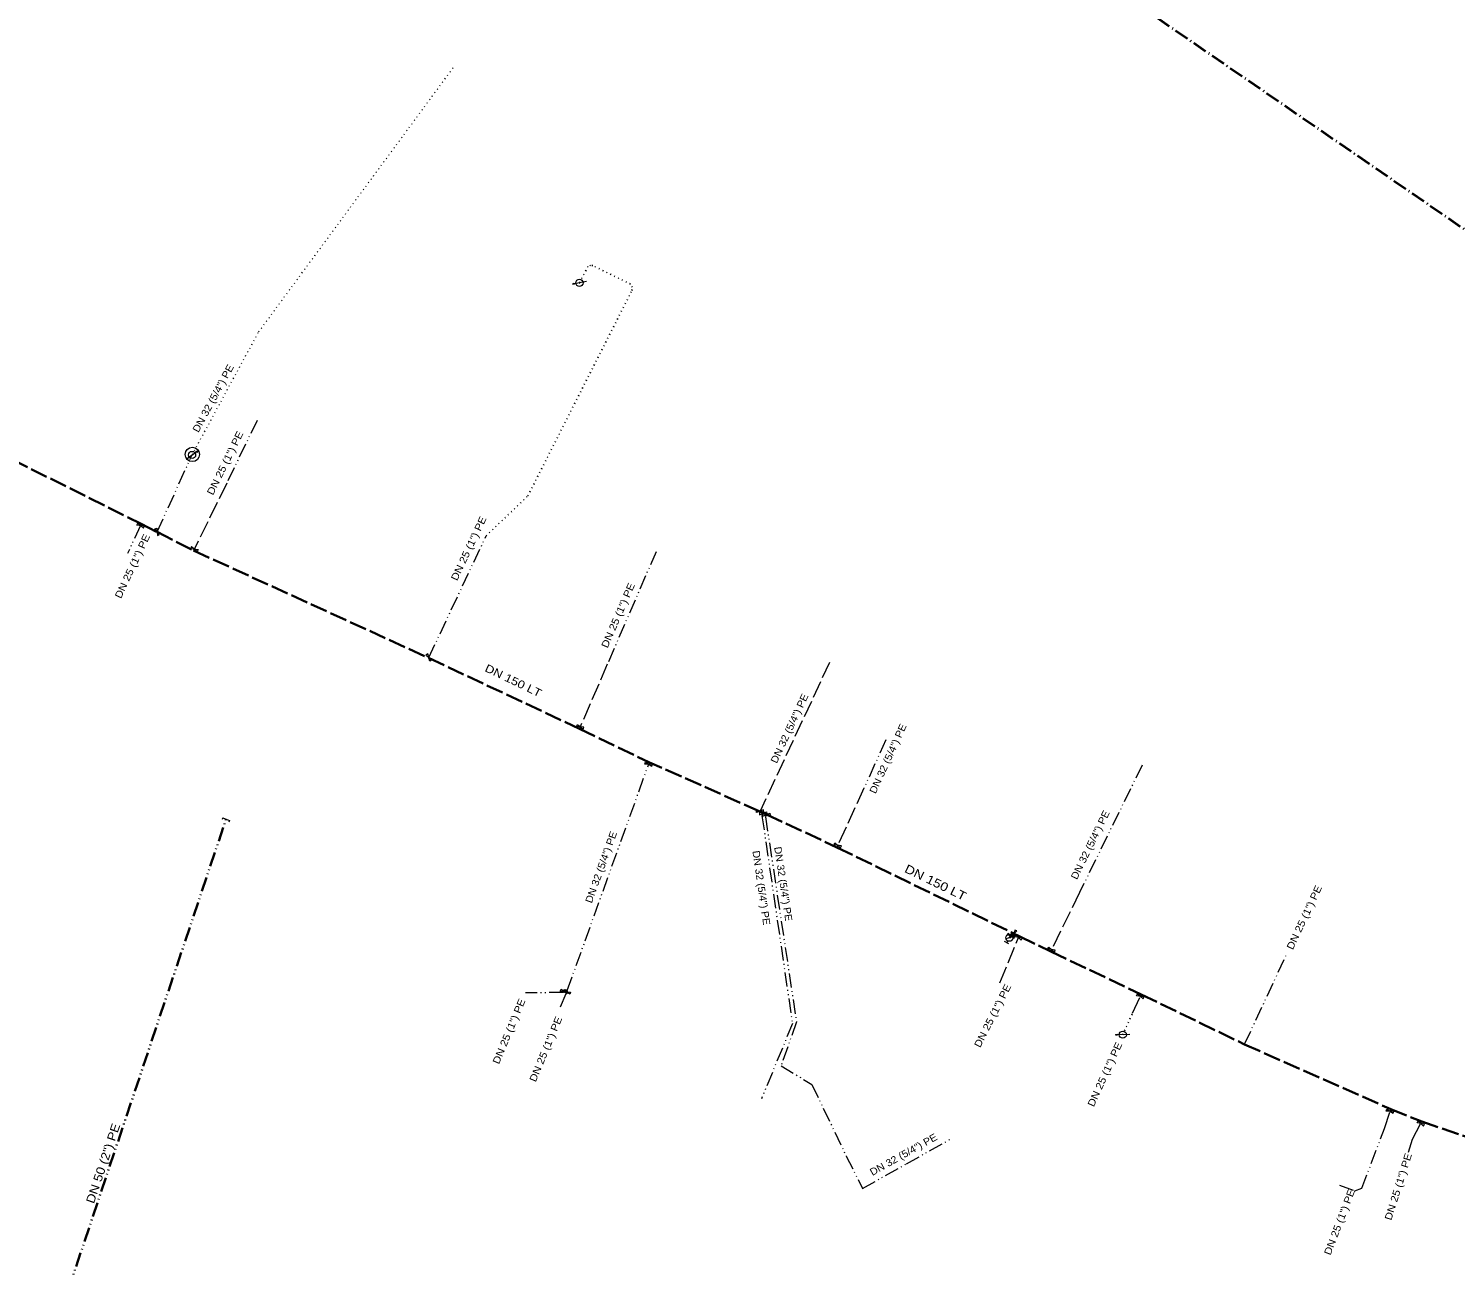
# Model space of a CAD drawing. Extents: x -635202 to -632824, y -1037605 to -1036177.
# Drawn here: x -634347.6 to -634148.5, y -1037187.1 to -1037014.4 of the extents above; entities that cross this region are included whole.
import ezdxf
from ezdxf.enums import TextEntityAlignment as Align

# ---------------------------------------------------------------- set-up
doc = ezdxf.new("R2010")
doc.units = 0
doc.header["$LTSCALE"] = 0.4
for name, pattern in [('DASH_DOUBLE_DOT', [9.2, 5, -1.2, 0.3, -1.2, 0.3, -1.2]), ('DOT_DASHED', [7.7, 5, -1.2, 0.3, -1.2]), ('DOTTED', [1.5, 0.3, -1.2]), ('LONG_DASHED', [7.5, 6, -1.5])]:
    doc.linetypes.add(name, pattern=pattern)
for name, color, linetype, lineweight in [('10', 7, 'Continuous', 13), ('12', 7, 'Continuous', 13), ('21', 7, 'LONG_DASHED', 35), ('22', 7, 'DASH_DOUBLE_DOT', 35), ('31', 7, 'LONG_DASHED', 13), ('32', 7, 'DASH_DOUBLE_DOT', 13), ('63', 7, 'DOT_DASHED', 40)]:
    doc.layers.add(name, color=color, linetype=linetype, lineweight=lineweight)
doc.layers.add('29', color=7, linetype='Continuous')
doc.layers.add('39', color=7, linetype='Continuous')

msp = doc.modelspace()

# ---------------------------------------------------------------- linework, layer by layer
at = {"layer": '10'}
for p, q in [((-634269.769, -1037049.723), (-634271.735, -1037050.094)), ((-634320.521, -1037124.53), (-634320.605, -1037124.765)), ((-634320.521, -1037124.53), (-634319.579, -1037124.864)), ((-634319.579, -1037124.864), (-634319.663, -1037125.1)), ((-634210.845, -1037142.104), (-634211.463, -1037141.775)), ((-634210.3, -1037141.087), (-634211.256, -1037141.379)), ((-634211.013, -1037141.674), (-634211.154, -1037141.939)), ((-634193.959, -1037154.713), (-634195.957, -1037154.796))]:
    msp.add_line(p, q, dxfattribs=at)
for points in [[(-634271.439, -1037050.143), (-634271.735, -1037050.094), (-634271.478, -1037049.94)], [(-634195.672, -1037154.888), (-634195.957, -1037154.796), (-634195.681, -1037154.682)]]:
    msp.add_lwpolyline(points, dxfattribs=at)
for points in [[(-634331.466, -1037083.828), (-634332.501, -1037083.689), (-634332.377, -1037083.416), (-634331.59, -1037084.102)], [(-634329.32, -1037085.018), (-634329.996, -1037084.222), (-634329.721, -1037084.101), (-634329.595, -1037085.138)], [(-634324.982, -1037086.931), (-634323.95, -1037087.091), (-634324.08, -1037087.362), (-634324.853, -1037086.66)], [(-634292.161, -1037101.814), (-634291.384, -1037102.512), (-634291.641, -1037102.668), (-634291.905, -1037101.657)], [(-634270.125, -1037111.875), (-634271.162, -1037111.753), (-634271.043, -1037111.478), (-634270.245, -1037112.151)], [(-634260.568, -1037117.043), (-634261.612, -1037117.03), (-634261.523, -1037116.744), (-634260.658, -1037117.33)], [(-634245.061, -1037123.377), (-634246.03, -1037123.764), (-634246.057, -1037123.465), (-634245.034, -1037123.675)], [(-634245.613, -1037124.078), (-634244.653, -1037123.665), (-634244.619, -1037123.964), (-634245.647, -1037123.78)], [(-634245.154, -1037124.294), (-634244.2, -1037123.871), (-634244.162, -1037124.168), (-634245.193, -1037123.997)], [(-634234.194, -1037128.426), (-634235.229, -1037128.288), (-634235.106, -1037128.014), (-634234.318, -1037128.699)], [(-634210.022, -1037140.155), (-634210.19, -1037141.185), (-634210.46, -1037141.054), (-634209.752, -1037140.286)], [(-634210.035, -1037141.052), (-634211.065, -1037140.884), (-634210.934, -1037140.614), (-634210.166, -1037141.321)], [(-634208.987, -1037141.302), (-634210.011, -1037141.1), (-634209.871, -1037140.835), (-634209.127, -1037141.567)], [(-634204.368, -1037142.967), (-634205.398, -1037142.796), (-634205.265, -1037142.527), (-634204.5, -1037143.236)], [(-634272.378, -1037148.743), (-634273.422, -1037148.701), (-634273.324, -1037148.418), (-634272.476, -1037149.026)], [(-634273.051, -1037148.771), (-634272.009, -1037148.827), (-634272.11, -1037149.11), (-634272.95, -1037148.488)], [(-634191.997, -1037149.487), (-634193.031, -1037149.341), (-634192.906, -1037149.069), (-634192.123, -1037149.76)], [(-634157.155, -1037165.43), (-634158.199, -1037165.415), (-634158.108, -1037165.129), (-634157.245, -1037165.716)], [(-634152.868, -1037167.24), (-634153.893, -1037167.041), (-634153.753, -1037166.776), (-634153.007, -1037167.506)]]:
    msp.add_lwpolyline(points, close=True, dxfattribs=at)
for centre, radius in [((-634270.752, -1037049.908), 0.5), ((-634324.7521, -1037073.8308), 1), ((-634210.7789, -1037141.2331), 0.5), ((-634194.958, -1037154.754), 0.5)]:
    msp.add_circle(centre, radius, dxfattribs=at)
at = {"layer": '12'}
msp.add_line((-634325.612, -1037074.485), (-634323.978, -1037073.331), dxfattribs=at)
msp.add_lwpolyline([(-634324.268, -1037073.41), (-634323.978, -1037073.331), (-634324.15, -1037073.577)], dxfattribs=at)
msp.add_circle((-634324.7949, -1037073.9078), 0.5, dxfattribs=at)
at = {"layer": '21'}
for p, q in [((-634371.382, -1037063.807), (-634331.877, -1037083.532)), ((-634331.877, -1037083.532), (-634329.672, -1037084.651)), ((-634329.672, -1037084.651), (-634324.576, -1037087.236)), ((-634324.576, -1037087.236), (-634291.795, -1037102.21)), ((-634291.795, -1037102.21), (-634270.759, -1037112.091)), ((-634270.759, -1037112.091), (-634261.001, -1037116.773)), ((-634245.566, -1037123.615), (-634261.001, -1037116.773)), ((-634244.66, -1037124.039), (-634234.828, -1037128.632)), ((-634234.828, -1037128.632), (-634210.348, -1037140.552)), ((-634210.55, -1037140.968), (-634210.779, -1037141.233)), ((-634210.348, -1037140.552), (-634210.55, -1037140.968)), ((-634210.106, -1037140.67), (-634209.401, -1037141.013)), ((-634209.401, -1037141.013), (-634205.007, -1037143.153)), ((-634205.007, -1037143.153), (-634192.38, -1037149.146)), ((-634177.973, -1037156.1), (-634157.582, -1037165.138)), ((-634157.582, -1037165.138), (-634153.252, -1037166.87)), ((-634153.252, -1037166.87), (-634141.09, -1037171.014))]:
    msp.add_line(p, q, dxfattribs=at)
for points in [[(-634245.566, -1037123.615), (-634245.113, -1037123.827), (-634245.113, -1037123.827)], [(-634245.113, -1037123.827), (-634244.66, -1037124.039), (-634244.66, -1037124.039)], [(-634210.348, -1037140.552), (-634210.106, -1037140.67), (-634210.106, -1037140.67)], [(-634192.38, -1037149.146), (-634177.973, -1037156.1), (-634177.973, -1037156.1)]]:
    msp.add_lwpolyline(points, dxfattribs=at)
at = {"layer": '22'}
msp.add_lwpolyline([(-634345.987, -1037202.012), (-634342.145, -1037190.56), (-634320.05, -1037124.697)], dxfattribs=at)
at = {"layer": '31'}
for p, q in [((-634319.963, -1037077.857), (-634324.466, -1037087.011)), ((-634324.466, -1037087.011), (-634324.576, -1037087.236)), ((-634266.866, -1037103.1), (-634270.644, -1037111.814)), ((-634235.859, -1037102.837), (-634245.545, -1037123.57)), ((-634270.644, -1037111.814), (-634270.759, -1037112.091)), ((-634261.09, -1037117.037), (-634261.001, -1037116.773)), ((-634231.07, -1037120.378), (-634234.712, -1037128.357)), ((-634245.545, -1037123.57), (-634245.566, -1037123.615)), ((-634234.712, -1037128.357), (-634234.828, -1037128.632)), ((-634200.976, -1037134.923), (-634204.883, -1037142.882)), ((-634212.085, -1037147.525), (-634209.499, -1037141.201)), ((-634209.499, -1037141.201), (-634209.401, -1037141.013)), ((-634204.883, -1037142.882), (-634205.007, -1037143.153)), ((-634193.591, -1037151.755), (-634192.514, -1037149.414)), ((-634192.514, -1037149.414), (-634192.38, -1037149.146)), ((-634158.438, -1037167.828), (-634157.677, -1037165.422)), ((-634157.677, -1037165.422), (-634157.582, -1037165.138)), ((-634154.519, -1037169.312), (-634153.38, -1037167.141)), ((-634153.38, -1037167.141), (-634153.252, -1037166.87))]:
    msp.add_line(p, q, dxfattribs=at)
at = {"layer": '32', "linetype": 'DOTTED', "lineweight": 25}
for p, q in [((-634270.752, -1037049.908), (-634270.984, -1037050.351)), ((-634194.958, -1037154.754), (-634193.591, -1037151.755)), ((-634195.165, -1037155.209), (-634194.958, -1037154.754))]:
    msp.add_line(p, q, dxfattribs=at)
at = {"layer": '32'}
for p, q in [((-634324.794, -1037073.908), (-634324.752, -1037073.831)), ((-634331.983, -1037083.759), (-634333.799, -1037087.653)), ((-634331.877, -1037083.532), (-634331.983, -1037083.759)), ((-634329.672, -1037084.651), (-634329.658, -1037084.619)), ((-634291.773, -1037102.163), (-634283.761, -1037085.18)), ((-634260.061, -1037087.402), (-634266.866, -1037103.1)), ((-634291.795, -1037102.21), (-634291.773, -1037102.163)), ((-634272.447, -1037148.569), (-634261.09, -1037117.037)), ((-634192.261, -1037117.167), (-634200.976, -1037134.923)), ((-634245.113, -1037123.827), (-634245.133, -1037123.872)), ((-634244.66, -1037124.039), (-634244.677, -1037124.083)), ((-634177.952, -1037156.055), (-634172.191, -1037143.759)), ((-634272.53, -1037148.799), (-634272.447, -1037148.569)), ((-634225.111, -1037172.751), (-634219.064, -1037169.366)), ((-634155.083, -1037171.115), (-634154.519, -1037169.312))]:
    msp.add_line(p, q, dxfattribs=at)
at = {"layer": '32', "linetype": 'DOTTED'}
msp.add_lwpolyline([(-634324.752, -1037073.831), (-634315.507, -1037056.745), (-634288.263, -1037019.766)], dxfattribs=at)
at = {"layer": '32', "linetype": 'DOTTED', "lineweight": 25}
msp.add_lwpolyline([(-634283.761, -1037085.18), (-634277.946, -1037079.613), (-634263.425, -1037050.966), (-634263.394, -1037050.526), (-634263.645, -1037050.07), (-634268.894, -1037047.508), (-634269.208, -1037047.461), (-634269.554, -1037047.618), (-634270.752, -1037049.908)], dxfattribs=at)
at = {"layer": '32'}
for points in [[(-634315.73, -1037069.098), (-634319.963, -1037077.857), (-634319.963, -1037077.857)], [(-634329.658, -1037084.619), (-634324.842, -1037073.997), (-634324.794, -1037073.908)], [(-634227.993, -1037113.655), (-634231.07, -1037120.378), (-634231.07, -1037120.378)], [(-634245.133, -1037123.872), (-634245.288, -1037124.218), (-634241.04, -1037153.216), (-634245.35, -1037163.688)], [(-634244.677, -1037124.083), (-634244.797, -1037124.383), (-634240.476, -1037152.977), (-634242.624, -1037159.085), (-634238.328, -1037161.691), (-634233.538, -1037171.676), (-634231.249, -1037176.187), (-634225.111, -1037172.751)], [(-634272.9, -1037148.722), (-634272.972, -1037148.886), (-634278.266, -1037148.903)], [(-634273.396, -1037150.876), (-634272.53, -1037148.799), (-634272.53, -1037148.799)], [(-634272.447, -1037148.569), (-634272.691, -1037148.49), (-634272.832, -1037148.524), (-634272.9, -1037148.722)], [(-634177.973, -1037156.1), (-634177.952, -1037156.055), (-634177.952, -1037156.055)], [(-634164.705, -1037175.734), (-634162.582, -1037176.526), (-634161.6, -1037176.154), (-634158.438, -1037167.828)]]:
    msp.add_lwpolyline(points, dxfattribs=at)
at = {"layer": '63'}
msp.add_lwpolyline([(-635201.893, -1036293.521), (-635065.737, -1036176.522), (-634666.247, -1036562.377), (-634740.782, -1036634.185), (-633954.528, -1037175.019), (-633883.629, -1037007.77), (-632823.776, -1037286.822), (-632902.856, -1037604.96), (-633921.805, -1037365.902), (-634067.239, -1037477.705), (-635033.469, -1036827.795), (-634902.578, -1036625.096)], close=True, dxfattribs=at)

# ---------------------------------------------------------------- texts
at = {"layer": '29', "width": 1.2}
for height, rotation, p in [(1.1, 334.325, (-634280.2133, -1037105.8654)), (1.2, 334.037, (-634221.3327, -1037134.065))]:
    msp.add_text('DN 150 LT', height=height, rotation=rotation, dxfattribs=at).set_placement(p, align=Align.CENTER)
at = {"layer": '29', "width": 1.15}
msp.add_text('DN 50 (2") PE', height=1.2, rotation=71.455, dxfattribs=at).set_placement((-634338.49, -1037178.397))
at = {"layer": '39'}
for s, rotation, width, p in [('DN 32 (5/4") PE', 61.583, 1.1, (-634321.4147, -1037066.2449)), ('DN 25 (1") PE', 63.807, 1.15, (-634319.7332, -1037075.2517)), ('DN 25 (1") PE', 64.743, 1.15, (-634285.755, -1037087.1573)), ('DN 25 (1") PE', 64.988, 1.15, (-634332.6681, -1037089.6304)), ('DN 25 (1") PE', 66.564, 1.15, (-634264.9088, -1037096.4759)), ('DN 32 (5/4") PE', 64.9, 1.1, (-634240.999, -1037112.2511)), ('DN 32 (5/4") PE', 65.466, 1.1, (-634227.2598, -1037116.4616)), ('DN 32 (5/4") PE', 63.857, 1.1, (-634199.0428, -1037128.5033)), ('DN 32 (5/4") PE', 70.192, 1.1, (-634267.2612, -1037131.5564)), ('DN 32 (5/4") PE', 278.334, 1.1, (-634245.8626, -1037134.3455)), ('DN 32 (5/4") PE', 278.593, 1.1, (-634242.807, -1037133.8003)), ('DN 25 (1") PE', 64.896, 1.15, (-634169.1828, -1037138.6121)), ('DN 25 (1") PE', 63.127, 1.15, (-634212.6681, -1037152.332)), ('DN 25 (1") PE', 67.366, 1.15, (-634280.1195, -1037154.4764)), ('DN 25 (1") PE', 67.366, 1.15, (-634274.9905, -1037156.9594)), ('DN 25 (1") PE', 65.5, 1.15, (-634196.9965, -1037160.4913)), ('DN 32 (5/4") PE', 29.24, 1.1, (-634225.3102, -1037171.8986)), ('DN 25 (1") PE', 72.63, 1.15, (-634156.0481, -1037176.0933)), ('DN 25 (1") PE', 69.205, 1.15, (-634164.2606, -1037181.0575))]:
    msp.add_text(s, height=1, rotation=rotation, dxfattribs=dict(at, width=width)).set_placement(p, align=Align.CENTER)

doc.saveas('drawing.dxf')
